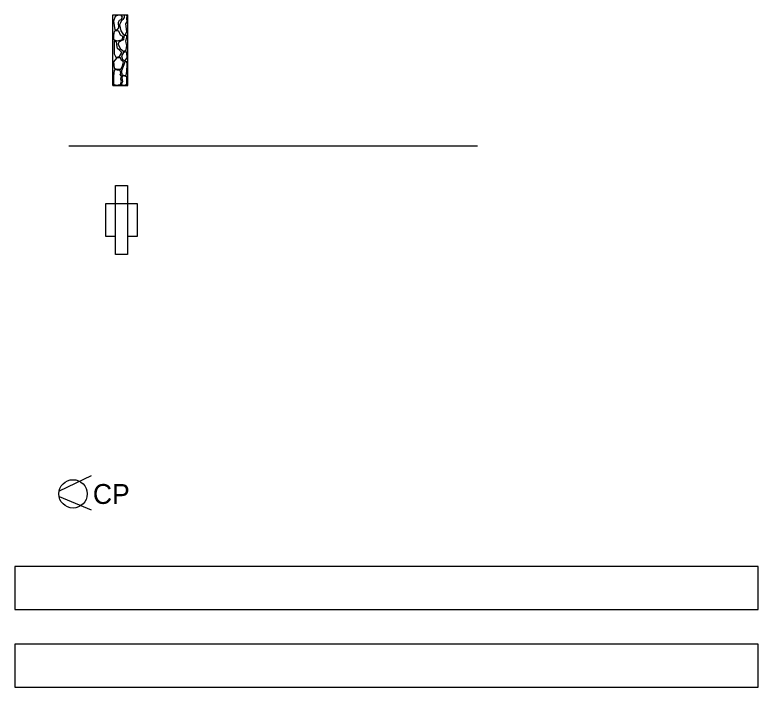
# Model space of a CAD drawing. Extents: x 2147712 to 2176316, y 2125036 to 2131746.
# Drawn here: x 2155450.7 to 2155731.4, y 2127071.3 to 2127325.1 of the extents above; entities that cross this region are included whole.
import ezdxf

# ---------------------------------------------------------------- set-up
doc = ezdxf.new("R2010")
doc.units = 0
doc.layers.add('ERSN CTRL', color=7, linetype='Continuous')
doc.layers.add('TURF EST', color=7, linetype='Continuous')

msp = doc.modelspace()

# ---------------------------------------------------------------- linework, layer by layer
at = {"layer": 'ERSN CTRL'}
for p, q in [((2155487.79, 2127298.38), (2155487.79, 2127325.11)), ((2155487.79, 2127325.11), (2155493.34, 2127325.11)), ((2155493.34, 2127298.38), (2155493.34, 2127325.11)), ((2155487.79, 2127298.38), (2155493.34, 2127298.38)), ((2155479.54, 2127151.04), (2155467.45, 2127145.33)), ((2155467.45, 2127143.24), (2155479.54, 2127138.23))]:
    msp.add_line(p, q, dxfattribs=at)
for points in [[(2155489.72, 2127325.03), (2155488.6, 2127324.46), (2155487.95, 2127322.77), (2155488.51, 2127319.47), (2155489.32, 2127319.47), (2155490.04, 2127320.2), (2155489.88, 2127322.29), (2155490.29, 2127323.1), (2155490.85, 2127323.42), (2155491.41, 2127324.22), (2155490.85, 2127325.03)], [(2155491.98, 2127325.03), (2155491.98, 2127324.14), (2155491.57, 2127323.34), (2155490.85, 2127322.77), (2155490.45, 2127321.89), (2155490.29, 2127321.32), (2155490.77, 2127319.07), (2155491.73, 2127317.54), (2155492.54, 2127317.7), (2155493.02, 2127318.83), (2155492.7, 2127321.73), (2155493.1, 2127322.45), (2155493.02, 2127323.74), (2155493.1, 2127324.79), (2155492.46, 2127325.03)], [(2155490.61, 2127317.46), (2155490.04, 2127318.91), (2155488.76, 2127319.07), (2155488.19, 2127318.83), (2155488.03, 2127317.38), (2155488.03, 2127315.85), (2155489.4, 2127315.29), (2155491.41, 2127315.85), (2155491.57, 2127316.98)], [(2155492.86, 2127317.38), (2155492.22, 2127317.38), (2155491.9, 2127316.9), (2155491.73, 2127315.69), (2155490.85, 2127315.29), (2155490.21, 2127314.97), (2155489.88, 2127314.64), (2155489.72, 2127314.08), (2155490.45, 2127312.39), (2155491.9, 2127311.26), (2155492.78, 2127311.91), (2155493.02, 2127313.6), (2155492.78, 2127314.56), (2155492.7, 2127315.29), (2155493.02, 2127316.58), (2155493.02, 2127316.9)], [(2155489.48, 2127312.39), (2155489.4, 2127313.03), (2155489.16, 2127314.88), (2155488.19, 2127315.21), (2155488.19, 2127313.19), (2155488.19, 2127310.38), (2155488.92, 2127309.09), (2155490.29, 2127309.33), (2155491.09, 2127310.94), (2155490.21, 2127311.83)], [(2155492.78, 2127311.18), (2155491.73, 2127310.94), (2155491.01, 2127309.65), (2155491.41, 2127308.2), (2155492.3, 2127307.8), (2155493.1, 2127308.93), (2155493.02, 2127310.78)], [(2155491.73, 2127307.32), (2155491.01, 2127307.88), (2155490.61, 2127308.93), (2155489.72, 2127308.93), (2155489.08, 2127308.77), (2155488.03, 2127307.4), (2155488.19, 2127304.98), (2155489.16, 2127304.58), (2155490.77, 2127304.58), (2155491.41, 2127305.87)], [(2155493.02, 2127307.56), (2155492.3, 2127307.32), (2155491.9, 2127306.27), (2155491.01, 2127304.02), (2155491.09, 2127302.49), (2155492.78, 2127302.25), (2155493.02, 2127303.86), (2155493.1, 2127306.19)], [(2155491.01, 2127302.01), (2155490.53, 2127302.57), (2155490.77, 2127303.13), (2155490.45, 2127304.18), (2155489.4, 2127304.18), (2155488.51, 2127304.42), (2155488.19, 2127304.18), (2155488.03, 2127301.92), (2155488.03, 2127299.99), (2155488.03, 2127298.95), (2155488.92, 2127298.62), (2155490.61, 2127298.79), (2155491.01, 2127300.07), (2155490.77, 2127300.88)], [(2155493.02, 2127301.76), (2155491.57, 2127302.17), (2155491.09, 2127301.36), (2155491.33, 2127299.99), (2155490.85, 2127298.79), (2155492.3, 2127298.62), (2155493.02, 2127298.95), (2155493.02, 2127300.32)]]:
    msp.add_lwpolyline(points, close=True, dxfattribs=at)
for points in [[(2155488.03, 2127307.08), (2155488.03, 2127307.08)], [(2155491.98, 2127298.38), (2155491.98, 2127298.38), (2155491.98, 2127298.38), (2155491.57, 2127298.38), (2155491.57, 2127298.38), (2155491.17, 2127298.38), (2155490.77, 2127298.38), (2155490.61, 2127298.38)], [(2155471.11, 2127275.61), (2155625.44, 2127275.61)], [(2155488.8, 2127254.88), (2155488.8, 2127260.67), (2155493.24, 2127260.67), (2155493.24, 2127254.88)], [(2155493.24, 2127254.88), (2155493.24, 2127234.67), (2155488.8, 2127234.67), (2155488.8, 2127254.88)], [(2155493.24, 2127241.61), (2155497.07, 2127241.61), (2155497.07, 2127253.72), (2155484.96, 2127253.72), (2155484.96, 2127241.61), (2155488.8, 2127241.61)]]:
    msp.add_lwpolyline(points, dxfattribs=at)
msp.add_circle((2155472.7, 2127144.28), 5.35, dxfattribs=at)
at = {"layer": 'TURF EST'}
for points in [[(2155450.74, 2127100.64), (2155731.41, 2127100.64), (2155731.41, 2127116.81), (2155450.74, 2127116.81)], [(2155450.74, 2127071.31), (2155731.41, 2127071.31), (2155731.41, 2127087.48), (2155450.74, 2127087.48)]]:
    msp.add_lwpolyline(points, close=True, dxfattribs=at)

# ---------------------------------------------------------------- texts
at = {"layer": 'ERSN CTRL'}
msp.add_text('CP', height=7.5, dxfattribs=at).set_placement((2155480.2, 2127140.48))

doc.saveas('drawing.dxf')
